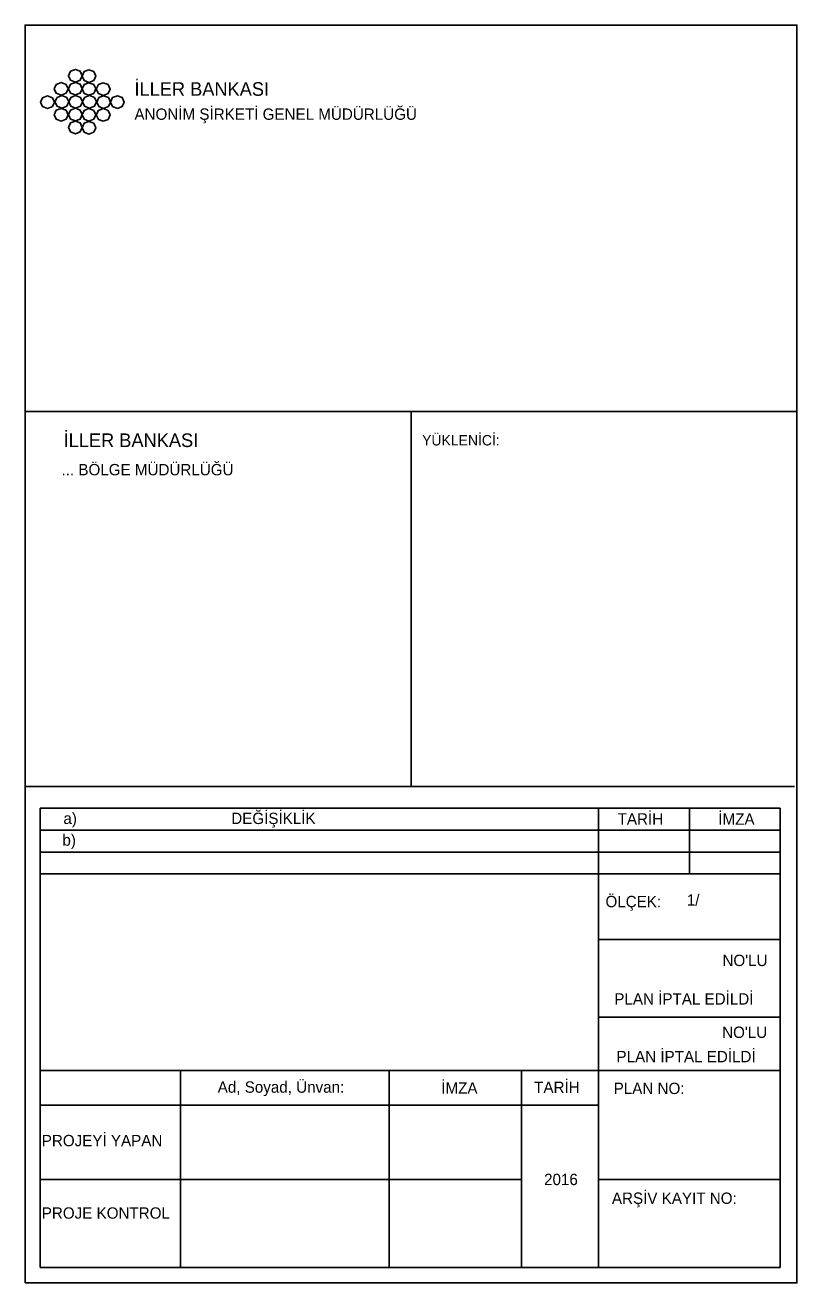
# Model space of a CAD drawing. Extents: x 641 to 811, y 0 to 277.
import ezdxf

# ---------------------------------------------------------------- set-up
doc = ezdxf.new("R2010")
doc.units = 0
doc.layers.add('Baslik', color=7, linetype='Continuous')
doc.layers.add('Level 53', color=7, linetype='Continuous')

msp = doc.modelspace()

# ---------------------------------------------------------------- linework, layer by layer
at = {"layer": 'Baslik'}
for p, q in [((641, 191.88), (811, 191.88)), ((726, 109.32), (726, 191.88)), ((807.33, 109.32), (641, 109.32)), ((810.48, 109.32), (807.33, 109.32)), ((807.33, 104.51), (644.31, 104.51)), ((644.31, 3.37), (644.31, 104.51)), ((767.33, 3.37), (767.33, 104.51)), ((787.33, 90.08), (787.33, 104.51)), ((807.33, 104.51), (807.33, 3.37)), ((807.33, 99.7), (644.31, 99.7)), ((807.33, 94.89), (644.31, 94.89)), ((807.33, 90.08), (644.31, 90.08)), ((807.33, 75.65), (767.33, 75.65)), ((807.33, 58.53), (767.33, 58.53)), ((807.33, 46.8), (644.31, 46.8)), ((675.2, 3.37), (675.2, 46.8)), ((721.17, 3.37), (721.17, 46.8)), ((750.33, 3.37), (750.33, 46.8)), ((767.33, 39.11), (644.31, 39.11)), ((750.33, 22.76), (644.31, 22.76)), ((807.33, 22.76), (767.33, 22.76)), ((807.33, 3.37), (644.31, 3.37))]:
    msp.add_line(p, q, dxfattribs=at)
for points in [[(653.59, 265.86), (653.14, 264.88), (652.07, 264.47), (651, 264.88), (650.55, 265.86), (651, 266.84), (652.07, 267.25), (653.14, 266.84)], [(653.53, 265.79), (653.97, 266.77), (655.04, 267.18), (656.12, 266.77), (656.56, 265.79), (656.12, 264.8), (655.04, 264.4), (653.97, 264.8)], [(647.42, 262.97), (647.86, 263.95), (648.94, 264.36), (650.01, 263.95), (650.45, 262.97), (650.01, 261.99), (648.94, 261.58), (647.86, 261.99)], [(653.59, 263.01), (653.14, 262.03), (652.07, 261.62), (651, 262.03), (650.55, 263.01), (651, 263.99), (652.07, 264.4), (653.14, 263.99)], [(653.53, 262.94), (653.97, 263.92), (655.04, 264.33), (656.12, 263.92), (656.56, 262.94), (656.12, 261.95), (655.04, 261.55), (653.97, 261.95)], [(659.27, 263.9), (659.72, 262.92), (659.27, 261.93), (658.2, 261.53), (657.13, 261.93), (656.68, 262.92), (657.13, 263.9), (658.2, 264.31)], [(646.99, 259.06), (645.92, 258.65), (644.84, 259.06), (644.4, 260.04), (644.84, 261.02), (645.92, 261.43), (646.99, 261.02), (647.43, 260.04)], [(648.02, 261.1), (649.09, 261.51), (650.16, 261.1), (650.6, 260.12), (650.16, 259.13), (649.09, 258.73), (648.02, 259.13), (647.57, 260.12)], [(652.12, 261.51), (653.2, 261.1), (653.64, 260.12), (653.2, 259.14), (652.12, 258.73), (651.05, 259.14), (650.61, 260.12), (651.05, 261.1)], [(653.67, 260.11), (654.11, 261.1), (655.19, 261.5), (656.26, 261.1), (656.7, 260.11), (656.26, 259.13), (655.19, 258.72), (654.11, 259.13)], [(657.21, 261.03), (658.28, 261.44), (659.35, 261.03), (659.8, 260.05), (659.35, 259.07), (658.28, 258.66), (657.21, 259.07), (656.77, 260.05)], [(661.31, 258.67), (660.24, 259.08), (659.79, 260.06), (660.24, 261.05), (661.31, 261.45), (662.38, 261.05), (662.82, 260.06), (662.38, 259.08)], [(647.42, 257.27), (647.86, 258.26), (648.94, 258.66), (650.01, 258.26), (650.45, 257.27), (650.01, 256.29), (648.94, 255.88), (647.86, 256.29)], [(653.59, 257.31), (653.14, 256.33), (652.07, 255.92), (651, 256.33), (650.55, 257.31), (651, 258.3), (652.07, 258.7), (653.14, 258.3)], [(653.53, 257.24), (653.97, 258.22), (655.04, 258.63), (656.12, 258.22), (656.56, 257.24), (656.12, 256.26), (655.04, 255.85), (653.97, 256.26)], [(659.27, 258.2), (659.72, 257.22), (659.27, 256.24), (658.2, 255.83), (657.13, 256.24), (656.68, 257.22), (657.13, 258.2), (658.2, 258.61)], [(653.59, 254.47), (653.14, 253.48), (652.07, 253.08), (651, 253.48), (650.55, 254.47), (651, 255.45), (652.07, 255.86), (653.14, 255.45)], [(653.53, 254.39), (653.97, 255.38), (655.04, 255.78), (656.12, 255.38), (656.56, 254.39), (656.12, 253.41), (655.04, 253), (653.97, 253.41)]]:
    msp.add_lwpolyline(points, close=True, dxfattribs=at)
for points in [[(653.59, 265.86), (653.14, 264.88), (652.07, 264.47), (651, 264.88), (650.55, 265.86), (651, 266.84), (652.07, 267.25), (653.14, 266.84), (653.59, 265.86)], [(653.53, 265.79), (653.97, 266.77), (655.04, 267.18), (656.12, 266.77), (656.56, 265.79), (656.12, 264.8), (655.04, 264.4), (653.97, 264.8), (653.53, 265.79)], [(647.42, 262.97), (647.86, 263.95), (648.94, 264.36), (650.01, 263.95), (650.45, 262.97), (650.01, 261.99), (648.94, 261.58), (647.86, 261.99), (647.42, 262.97)], [(653.59, 263.01), (653.14, 262.03), (652.07, 261.62), (651, 262.03), (650.55, 263.01), (651, 263.99), (652.07, 264.4), (653.14, 263.99), (653.59, 263.01)], [(653.53, 262.94), (653.97, 263.92), (655.04, 264.33), (656.12, 263.92), (656.56, 262.94), (656.12, 261.95), (655.04, 261.55), (653.97, 261.95), (653.53, 262.94)], [(659.27, 263.9), (659.72, 262.92), (659.27, 261.93), (658.2, 261.53), (657.13, 261.93), (656.68, 262.92), (657.13, 263.9), (658.2, 264.31), (659.27, 263.9)], [(646.99, 259.06), (645.92, 258.65), (644.84, 259.06), (644.4, 260.04), (644.84, 261.02), (645.92, 261.43), (646.99, 261.02), (647.43, 260.04), (646.99, 259.06)], [(648.02, 261.1), (649.09, 261.51), (650.16, 261.1), (650.6, 260.12), (650.16, 259.13), (649.09, 258.73), (648.02, 259.13), (647.57, 260.12), (648.02, 261.1)], [(652.12, 261.51), (653.2, 261.1), (653.64, 260.12), (653.2, 259.14), (652.12, 258.73), (651.05, 259.14), (650.61, 260.12), (651.05, 261.1), (652.12, 261.51)], [(653.67, 260.11), (654.11, 261.1), (655.19, 261.5), (656.26, 261.1), (656.7, 260.11), (656.26, 259.13), (655.19, 258.72), (654.11, 259.13), (653.67, 260.11)], [(657.21, 261.03), (658.28, 261.44), (659.35, 261.03), (659.8, 260.05), (659.35, 259.07), (658.28, 258.66), (657.21, 259.07), (656.77, 260.05), (657.21, 261.03)], [(661.31, 258.67), (660.24, 259.08), (659.79, 260.06), (660.24, 261.05), (661.31, 261.45), (662.38, 261.05), (662.82, 260.06), (662.38, 259.08), (661.31, 258.67)], [(647.42, 257.27), (647.86, 258.26), (648.94, 258.66), (650.01, 258.26), (650.45, 257.27), (650.01, 256.29), (648.94, 255.88), (647.86, 256.29), (647.42, 257.27)], [(653.59, 257.31), (653.14, 256.33), (652.07, 255.92), (651, 256.33), (650.55, 257.31), (651, 258.3), (652.07, 258.7), (653.14, 258.3), (653.59, 257.31)], [(653.53, 257.24), (653.97, 258.22), (655.04, 258.63), (656.12, 258.22), (656.56, 257.24), (656.12, 256.26), (655.04, 255.85), (653.97, 256.26), (653.53, 257.24)], [(659.27, 258.2), (659.72, 257.22), (659.27, 256.24), (658.2, 255.83), (657.13, 256.24), (656.68, 257.22), (657.13, 258.2), (658.2, 258.61), (659.27, 258.2)], [(653.59, 254.47), (653.14, 253.48), (652.07, 253.08), (651, 253.48), (650.55, 254.47), (651, 255.45), (652.07, 255.86), (653.14, 255.45), (653.59, 254.47)], [(653.53, 254.39), (653.97, 255.38), (655.04, 255.78), (656.12, 255.38), (656.56, 254.39), (656.12, 253.41), (655.04, 253), (653.97, 253.41), (653.53, 254.39)]]:
    msp.add_lwpolyline(points, dxfattribs=at)
at = {"layer": 'Level 53'}
msp.add_lwpolyline([(641, 0), (811, 0), (811, 277), (641, 277)], close=True, dxfattribs=at)

# ---------------------------------------------------------------- texts
at = {"layer": 'Baslik'}
for s, height, p in [('İLLER BANKASI', 3, (665.08, 261.44)), ('ANONİM ŞİRKETİ GENEL MÜDÜRLÜĞÜ', 2.5, (665.08, 256.15)), ('İLLER BANKASI', 3, (649.47, 184.08)), ('YÜKLENİCİ:', 2.3, (728.45, 184.43)), ('... BÖLGE MÜDÜRLÜĞÜ', 2.5, (649.01, 177.85)), ('a)', 2.5, (649.43, 101.05)), ('DEĞİŞİKLİK', 2.5, (686.41, 101.05)), ('TARİH', 2.5, (771.52, 100.93)), ('İMZA', 2.5, (793.7, 100.88)), ('b)', 2.5, (649.21, 96.28)), ('ÖLÇEK:', 2.5, (768.84, 82.73)), ('1/     ', 2.5, (786.76, 83.06)), ("NO'LU", 2.5, (794.61, 69.77)), ('PLAN İPTAL EDİLDİ', 2.5, (770.79, 61.28)), ("NO'LU", 2.5, (794.54, 53.94)), ('PLAN İPTAL EDİLDİ', 2.5, (771.27, 48.58)), ('Ad, Soyad, Ünvan:', 2.5, (683.42, 41.87)), ('İMZA', 2.5, (732.67, 41.66)), ('TARİH', 2.5, (753.13, 41.82)), ('PLAN NO:', 2.5, (770.65, 41.58)), ('PROJEYİ YAPAN', 2.5, (644.66, 30.08)), ('2016', 2.5, (755.32, 21.53)), ('ARŞİV KAYIT NO:', 2.5, (770.26, 17.39)), ('PROJE KONTROL', 2.5, (644.66, 14.13))]:
    msp.add_text(s, height=height, dxfattribs=at).set_placement(p)

doc.saveas('drawing.dxf')
